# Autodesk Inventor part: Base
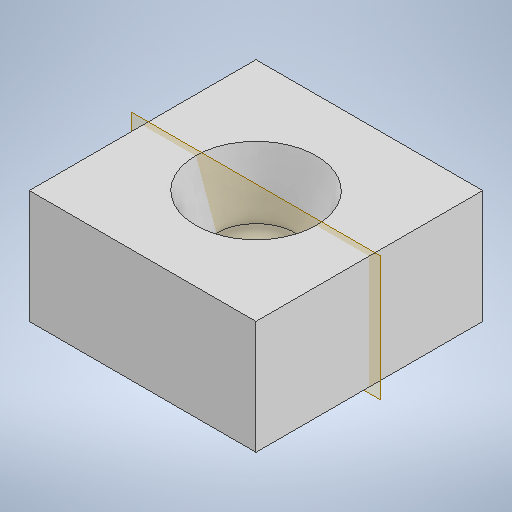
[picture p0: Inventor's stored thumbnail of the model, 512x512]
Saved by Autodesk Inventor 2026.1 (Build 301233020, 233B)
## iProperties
Created: 2026-11
Part Number: Base
Material: Generic
Document SubType Name: Modeling
Designer: hp
Density: 1 g/cm^3
Appearance: Default
Author: hp
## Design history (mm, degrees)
sketch "Sketch1"
  geometry: L1 (-20, 20)-(20, 20); L2 (20, 20)-(20, -20); L3 (20, -20)-(-20, -20); L4 (-20, -20)-(-20, 20); L5 (-20, 20)-(20, -20); L6 (20, 20)-(-20, -20); C1 r 10 at (0, 0); 1 further point
  constraints: 12 end point, 2 midpoint, 2 parallel, 1 centre point, 1 coincident, 1 horizontal, 1 perpendicular
  dimensions: "d0" = 40 distance of L2.end L3.end; "d1" = 40 distance of L1.end L2.end; "d2" = 20 diameter of C1
extrude "Extrusion1" new body sketch "Sketch1" distance "d3" = 20; taper "d4" = 0 deg
workplane "Work Plane1"
sketch "Sketch2"
  geometry: L1 (20, 0)-(20, 20); L2 (40, 20)-(0, 20) reference; L3 (20, 10)-(27, 10); L4 (27, 10)-(30.64, 20)
  constraints: 6 end point, 2 midpoint, 1 horizontal, 1 point on line
  dimensions: "d5" = 7 distance of L3.start L3.end; "d6" = 110 deg angle of L3 L4
revolve "Revolution1" sketch "Sketch2" stored, may be unused: angle "d7" = 360 deg
body "Solid1"
